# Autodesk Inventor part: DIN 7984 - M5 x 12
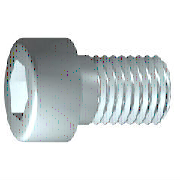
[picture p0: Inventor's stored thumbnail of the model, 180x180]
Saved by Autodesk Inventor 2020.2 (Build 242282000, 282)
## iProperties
Manager: www.cadconsulting.pl
Company: Fabian Stasiak CAD Consulting
Created: 2011-02
Part Number: DIN 7984 - M5 x 12
Material: Stal, miękka
Description: Wkręt z łbem półkolistym walcowym
Document SubType Name: Modeling
Standard: DIN 7984
Designer: F.Stasiak
Standard Revision: 1985
Standards Organization: DIN
Language: pl-PL
Size Designation: M5 x 12
Categories: <MemberInstance><Categories><Category DisplayName="Mocowania" InternalName="e4da775c-781d-43d5-af7c-5136215cf5a6" Mnemonic="FSTN"><Category DisplayName="Śruby"
Density: 7.86 g/cm^3
Appearance: Metal-Stal
Mass: 3.19901 g
Surface Area: 4.14287 cm^2
Volume: 0.406998 cm^3
IsCustomPart: 0
Author: F.Stasiak
Subject: Zbiór ćwiczeń. Autodesk Inventor 2020. Kurs podstawowy
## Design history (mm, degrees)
sketch "Szkic1"
  geometry: L1 (0.2, 0)-(12, 0); L2 (12, 0)-(12, 2.5); L3 (12, 2.5)-(2.4, 2.5); L4 (2.4, 2.5)-(1.909, 2.5); L5 (1.909, 2.5)-(0, 2.5); L6 (0, 2.5)-(0, 4.25); L7 (0, 4.25)-(-3.5, 4.25); L8 (-3.5, 4.25)-(-3.5, 1.732); L9 (-3.5, 1.732)-(-0.8, 1.732); L10 (-0.8, 1.732)-(0.2, 0); L11 (-6.6, 0)-(15.1, 0) reference; L12 (0, -0.85)-(0, 5.1) reference; L13 (2.4, 2.5)-(0, 2.5)
  constraints: 22 end point, 6 parallel, 2 collinear, 2 perpendicular, 1 horizontal, 1 point on line
  dimensions: "d1" = 9.6 distance from line of L3.end L2 (= GEL); "d2" = 0.49086 distance of L4.end L3.end (computed from GAL); "d3" = 3.5 distance between parallel lines of L8 L6 (= KOH); "d4" = 2.7 distance of L8.end L9.end (= INTI); "d5" = 60 deg angle of L10 L1; "d6" = 5 diameter of L3 L1 (= GD); "d7" = 5 diameter of L5 L1 (= BDM); "d8" = 3.4641 diameter of L9 L1 (= 1.1547 x SW); "d9" = 8.5 diameter of L7 L1 (= KOD); "d26" = 12 distance between parallel lines of L12 L2 (= NLG)
revolve "Bryła" sketch "Szkic1" stored, may be unused: angle "d10" = 90 deg
sketch "Szkic2"
  geometry: L1 (0, -5.95)-(0, 5.95) reference; L2 (-5.95, 0)-(5.95, 0) reference; L3 (1.732, 0)-(0.866, -1.5); L4 (0.866, -1.5)-(-0.866, -1.5); L5 (-0.866, -1.5)-(-1.732, 0); L6 (-1.732, 0)-(-0.866, 1.5); L7 (-0.866, 1.5)-(0.866, 1.5); L8 (0.866, 1.5)-(1.732, 0); 2 further points
  constraints: 12 end point, 1 coincident, 1 horizontal alignment, 1 point on line, 12 other
extrude "Szczelina" join sketch "Szkic2" stored distance "d11" = 10; taper "d12" = 0 deg
workplane "Work Plane1"
fillet "Fillet2" dims "d30" = 0.1 (= R)
body "Solid1"
fillet "Zaokrąglenie1" dims "d17" = 0.5 (= RR)
feature "Gwint" dims "d13" = 9.6 (= GEL), "d14" = 0
chamfer "Faza1" distance "d15" = 0.49076 (= -0.5 x SPD + 0.5 x GD); stored, may be unused: second distance "d16" = 0.49076 (= GUL), angle "d27" = 45 deg
other parameters: "GD" = 5 (= NND) [user parameter; used in 2 equation terms], "NLG" = 12 [user parameter; used in 1 equation term], "GEL" = 9.6 [user parameter; used in 2 equation terms], "KOD" = 8.5 [user parameter; used in 1 equation term], "KOH" = 3.5 [user parameter; used in 1 equation term], "INTI" = 2.7 [user parameter; used in 1 equation term], "GAL" = 0.49076 (= 0.61345 x PTC) [user parameter; used in 1 equation term], "GUL" = 0.49076 (= 0.61345 x PTC) [user parameter; used in 1 equation term], "BDM" = 5 (= NND) [user parameter; used in 1 equation term], "SW" = 3 [user parameter; used in 2 equation terms], "RR" = 0.5 [user parameter; used in 1 equation term], "SPD" = 4.01848 (= NND - 1.2269 x PTC) [user parameter; used in 1 equation term], "d19" = 0, "d28" = 0, "d29" = 0, "R" = 0.1 [user parameter; used in 1 equation term], "TOA" = 30 deg [user parameter], "GD1" = 4.01848 (= THREADDIA - 1.2269 x PTC) [user parameter], "THREADDIA" = 5 [user parameter; used in 1 equation term], "FAWI" = 45 deg [user parameter], "ANG" = 120 deg [user parameter], "TPU" = 12.5 (computed from PTC) [user parameter], "PTC" = 0.8 [user parameter; used in 5 equation terms], "NND" = 5 [user parameter; used in 3 equation terms], "E0" = 3.465 (= 1.155 x SW) [user parameter]
